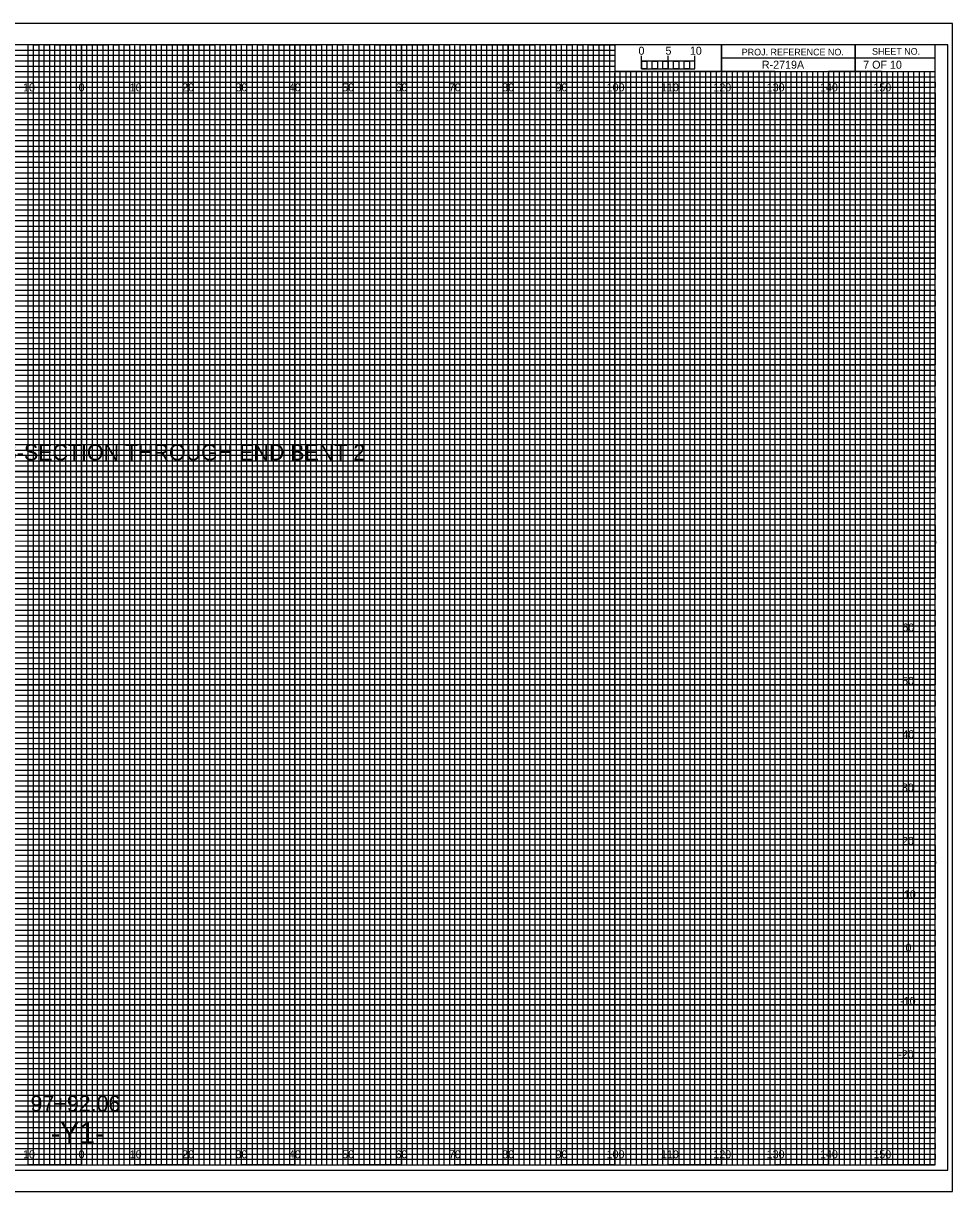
# Model space of a CAD drawing. Extents: x -13 to 886, y -5 to 434.
# Drawn here: x 149.1 to 323.3, y 215 to 434 of the extents above; entities that cross this region are included whole.
import ezdxf

# ---------------------------------------------------------------- set-up
doc = ezdxf.new("R2010")
doc.units = 0
for name, color, linetype in [('Prop Road Sect_ Boring - Header Labels from Geopak', 7, 'Continuous'), ('Prop XS Alignment Label', 7, 'Continuous'), ('Prop XS Bar Scale Labels', 7, 'Continuous'), ('Prop XS Elevation Labels', 7, 'Continuous'), ('Prop XS Offset Labels', 7, 'Continuous'), ('Prop XS Project Number', 7, 'Continuous'), ('Prop XS Sheet Number', 7, 'Continuous'), ('Prop XS Station Labels', 7, 'Continuous'), ('Sheet Cross Section CELL', 7, 'Continuous'), ('Sheet Cross Section Grid Major CELL', 7, 'Continuous'), ('Sheet Cross Section Grid Middle CELL', 7, 'Continuous'), ('Sheet Cross Section Grid Minor 1 CELL', 7, 'Continuous'), ('Sheet Cross Section Grid Minor 2 CELL', 7, 'Continuous'), ('Sheet Cross Section Scale CELL', 7, 'Continuous'), ('Sheet Cutting Line CELL', 7, 'Continuous'), ('Sheet DOT Grid CELL', 7, 'Continuous'), ('Sheet Plot Border Inside CELL', 7, 'Continuous'), ('Sheet Plot Border Outside CELL', 7, 'Continuous')]:
    doc.layers.add(name, color=color, linetype=linetype)

msp = doc.modelspace()

# ---------------------------------------------------------------- linework, layer by layer
at = {"layer": 'Sheet Cross Section CELL'}
for p, q in [((305, 430), (305, 425)), ((305, 425), (305, 430)), ((280, 427.5), (280, 425)), ((320, 427.49), (280, 427.49)), ((280, 425), (320, 425))]:
    msp.add_line(p, q, dxfattribs=at)
for points in [[(320, 430), (0, 430), (0, 220), (320, 220)], [(280, 430), (260, 430), (260, 425.03), (280, 425.03)], [(320, 430), (280, 430), (280, 425), (320, 425)]]:
    msp.add_lwpolyline(points, close=True, dxfattribs=at)
at = {"layer": 'Sheet Cross Section Grid Major CELL'}
for p, q in [((150, 430), (140, 430)), ((150, 220), (150, 430)), ((170, 430), (160, 430)), ((160, 430), (160, 220)), ((170, 220), (170, 430)), ((190, 430), (180, 430)), ((180, 430), (180, 220)), ((190, 220), (190, 430)), ((210, 430), (200, 430)), ((200, 430), (200, 220)), ((210, 220), (210, 430)), ((230, 430), (220, 430)), ((220, 430), (220, 220)), ((230, 220), (230, 430)), ((250, 430), (240, 430)), ((240, 430), (240, 220)), ((250, 220), (250, 430)), ((260, 430), (260, 220)), ((270, 220), (270, 425)), ((290, 425), (280, 425)), ((280, 425), (280, 220)), ((290, 220), (290, 425)), ((310, 425), (300, 425)), ((300, 425), (300, 220)), ((310, 220), (310, 425)), ((160, 220), (150, 220)), ((180, 220), (170, 220)), ((200, 220), (190, 220)), ((220, 220), (210, 220)), ((240, 220), (230, 220)), ((260, 220), (250, 220)), ((280, 220), (270, 220)), ((300, 220), (290, 220)), ((320, 220), (310, 220)), ((320, 220), (320, 220))]:
    msp.add_line(p, q, dxfattribs=at)
for points in [[(0, 420), (320, 420), (320, 410), (0, 410)], [(0, 400), (320, 400), (320, 390), (0, 390)], [(0, 380), (320, 380), (320, 370), (0, 370)], [(0, 360), (320, 360), (320, 350), (0, 350)], [(0, 340), (320, 340), (320, 330), (0, 330)], [(0, 320), (320, 320), (320, 310), (0, 310)], [(0, 300), (320, 300), (320, 290), (0, 290)], [(0, 280), (320, 280), (320, 270), (0, 270)], [(0, 260), (320, 260), (320, 250), (0, 250)], [(0, 240), (320, 240), (320, 230), (0, 230)]]:
    msp.add_lwpolyline(points, dxfattribs=at)
at = {"layer": 'Sheet Cross Section Grid Middle CELL'}
for points in [[(145, 220), (155, 220), (155, 430), (165, 430), (165, 220), (175, 220), (175, 430), (185, 430), (185, 220), (195, 220), (195, 430), (205, 430), (205, 220), (215, 220), (215, 430), (225, 430), (225, 220), (235, 220), (235, 430), (245, 430), (245, 220), (255, 220), (255, 430), (259.93, 430), (260, 430), (260, 425), (264.99, 425), (264.99, 220), (275, 220), (275, 425), (285, 425), (285, 220), (295, 220), (295, 425), (305, 425), (305, 220), (315, 220), (315, 425)], [(0, 425), (275, 425)], [(0, 405), (320, 405), (320, 415), (0, 415)], [(0, 385), (320, 385), (320, 395), (0, 395)], [(0, 365), (320, 365), (320, 375), (0, 375)], [(0, 345), (320, 345), (320, 355), (0, 355)], [(0, 325), (320, 325), (320, 335), (0, 335)], [(0, 305), (320, 305), (320, 315), (0, 315)], [(0, 285), (320, 285), (320, 295), (0, 295)], [(0, 265), (320, 265), (320, 275), (0, 275)], [(0, 245), (320, 245), (320, 255), (0, 255)], [(0, 225), (320, 225), (320, 235), (0, 235)]]:
    msp.add_lwpolyline(points, dxfattribs=at)
at = {"layer": 'Sheet Cross Section Grid Minor 1 CELL'}
for p, q in [((0, 429), (260, 429)), ((260, 427.98), (0, 427.98)), ((260, 429), (260, 427.98)), ((0, 427), (260, 427)), ((260, 425.89), (0, 425.89)), ((260, 427), (260, 425.89)), ((0, 424), (320, 424))]:
    msp.add_line(p, q, dxfattribs=at)
for points in [[(0, 423), (270, 423), (320, 423), (320, 422), (0, 422)], [(0, 421), (320, 421), (320, 419), (0, 419)], [(0, 418), (320, 418), (320, 417), (0, 416.98)], [(0, 416), (320, 416), (320, 414), (0, 414)], [(0, 413), (320, 413), (320, 412), (0, 412)], [(0, 411), (320, 411), (320, 409), (0, 409)], [(0, 408), (320, 408), (320, 407), (0, 407)], [(0, 406), (320, 406), (320, 404), (0, 404)], [(0, 403), (320, 403), (320, 402), (0, 402)], [(0, 401), (320, 401), (320, 399), (0, 399)], [(0, 398), (320, 398), (320, 397), (0, 397)], [(0, 396), (320, 396), (320, 393.95), (320, 393), (320, 392), (0, 392)], [(0, 394), (320, 394), (320, 393), (0, 393)], [(0, 391), (320, 391), (320, 389), (0, 389.03)], [(0, 389.03), (320, 389), (320, 388), (0, 388)], [(0, 387), (320, 387), (320, 386), (0, 386)], [(0, 384), (320, 384), (320, 383), (0, 383)], [(0, 382), (320, 382), (320, 381), (0, 381)], [(-0.07, 378.89), (320, 378.89), (320, 377.88), (-0.07, 377.88)], [(0, 377), (320, 377), (320, 376), (0, 376)], [(0, 374), (320, 374), (320, 373), (0, 373)], [(0, 372), (320, 372), (320, 371), (0, 371)], [(0, 369), (320, 369), (320, 368), (0, 368)], [(0, 367), (320, 367), (320, 366), (0, 366)], [(0, 364), (320, 364), (320, 363), (0, 363)], [(0, 362), (320, 362), (320, 361), (0, 361)], [(0, 359), (320, 359), (319.99, 357.98), (0, 358)], [(0, 357), (320, 357), (320, 356), (0, 356)], [(0, 354), (320, 354), (320, 353), (0, 353)], [(0, 352), (320, 352), (320, 351), (0, 351)], [(0, 349), (320, 349), (320, 348), (0, 348)], [(0, 347), (320, 347), (320, 346), (0, 346)], [(0, 344), (320, 344), (320, 343), (0, 343)], [(0, 342), (320, 342), (320, 341), (0, 341)], [(0, 339), (320, 339), (320, 338), (0, 338)], [(0, 336.99), (320.07, 336.91), (320, 336), (0, 336)], [(0, 334), (320, 334), (320, 333), (0, 333)], [(0, 332), (320, 332), (320, 331), (0, 331)], [(0, 329), (320, 329), (320, 328), (0, 328)], [(0, 327), (320, 327), (320, 326), (0, 326)], [(0, 324), (320, 324), (320, 323), (0, 323)], [(0, 322), (320, 322), (320, 321), (0, 321)], [(0, 319), (320, 319), (320, 318), (0, 318)], [(0, 317), (320, 317), (320, 316), (0, 316)], [(0, 314), (320, 314), (320, 313), (0, 313)], [(0, 312), (320, 312), (320, 311), (0, 311)], [(0, 309), (320, 309), (320, 308), (0, 308)], [(0, 307), (320, 307), (320, 306), (0, 306)], [(0, 304), (320, 304), (320, 303), (0, 303)], [(0, 302), (320, 302), (320, 301), (0, 301)], [(0, 299), (320, 299), (319.99, 297.98), (0, 298)], [(0, 297), (320, 297), (320, 296), (0, 296)], [(0, 294), (320, 294), (320, 293), (0, 293)], [(0, 292), (320, 292), (320, 291), (0, 291)], [(0, 289), (320, 289), (320, 288), (0, 288)], [(0, 287), (320, 287), (320, 286), (0, 286)], [(0, 284), (320, 284), (320, 283), (0, 283)], [(0, 282), (320, 282), (320, 281), (0, 281)], [(0, 279), (320, 279), (320, 278), (0, 278)], [(0, 276.99), (320.07, 276.91), (320, 276), (0, 276)], [(0, 274), (320, 274), (320, 273), (0, 273)], [(0, 272), (320, 272), (320, 271), (0, 271)], [(0, 269), (320, 269), (320, 268), (0, 268)], [(0, 267), (320, 267), (320, 266), (0, 266)], [(0, 264), (320, 264), (320, 263), (0, 263)], [(0, 262), (320, 262), (320, 261), (0, 261)], [(0, 259), (320, 259), (320, 258), (0, 258)], [(0, 257), (320, 257), (320, 256), (0, 256)], [(0, 254), (320, 254), (320, 253), (0, 253)], [(0, 252), (320, 252), (320, 251), (0, 251)], [(0, 249), (320, 249), (320, 248), (0, 248)], [(0, 247), (320, 247), (320, 246), (0, 246)], [(0, 244), (320, 244), (320, 243), (0, 243)], [(0, 242), (320, 242), (320, 241), (0, 241)], [(0, 239), (320, 239), (320, 238), (0, 238)], [(0, 237), (320, 237), (320, 236), (0, 236)], [(0, 234), (320, 234), (320, 233), (0, 233)], [(0, 232), (320, 232), (320, 231), (0, 231)], [(0, 229), (320, 229), (320, 228), (0, 228)], [(0, 227), (320, 227), (320, 226), (0, 226)], [(0, 224), (320, 224), (320, 223), (0, 223)], [(0, 222), (320, 222), (320, 221), (0, 221)]]:
    msp.add_lwpolyline(points, dxfattribs=at)
at = {"layer": 'Sheet Cross Section Grid Minor 2 CELL'}
for p, q in [((267, 425), (266.01, 425)), ((266.01, 425), (266.01, 220)), ((267, 220), (267, 425)), ((269, 425), (268, 425)), ((268, 425), (268, 220)), ((269, 220), (269, 425)), ((266.01, 220), (265, 220)), ((268, 220), (267, 220))]:
    msp.add_line(p, q, dxfattribs=at)
for points in [[(150, 220), (151, 220), (151, 430), (152, 430), (152, 220)], [(152, 220), (153, 220), (153, 430), (154, 430), (154, 220)], [(155, 220), (156, 220), (156, 430), (157, 430), (157, 220)], [(157, 220), (158, 220), (158, 430), (159, 430), (159, 220)], [(160, 220), (161, 220), (161, 430), (162, 430), (162, 220)], [(162, 220), (163, 220), (163, 430), (164, 430), (164, 220)], [(165, 220), (166, 220), (166, 430), (167, 430), (167, 220)], [(167, 220), (168, 220), (168, 430), (169, 430), (169, 220)], [(170, 220), (171, 220), (171, 430), (172, 430), (172, 220)], [(172, 220), (173, 220), (173, 430), (174, 430), (174, 220)], [(175, 220), (176, 220), (176, 430), (177, 430), (177, 220)], [(177, 220), (178, 220), (178, 430), (179, 430), (179, 220)], [(180, 220), (181, 220), (181, 430), (182, 430), (182, 220)], [(182, 220), (183, 220), (183, 430), (184, 430), (184, 220)], [(185, 220), (186, 220), (186, 430), (187, 430), (187, 220)], [(187, 220), (188, 220), (188, 430), (189, 430), (189, 220)], [(190, 220), (191, 220), (191, 430), (192, 430), (192, 220)], [(192, 220), (193, 220), (193, 430), (194, 430), (194, 220)], [(195, 220), (196, 220), (196, 430), (197, 430), (197, 220)], [(197, 220), (198, 220), (198, 430), (199, 430), (199, 220)], [(200, 220), (201, 220), (201, 430), (202, 430), (202, 220)], [(202, 220), (203, 220), (203, 430), (204, 430), (204, 220)], [(205, 220), (206, 220), (206, 430), (207, 430), (207, 220)], [(207, 220), (208, 220), (208, 430), (209, 430), (209, 220)], [(210, 220), (211, 220), (211, 430), (212, 430), (212, 220)], [(212, 220), (213, 220), (213, 430), (214, 430), (214, 220)], [(215, 220), (216, 220), (216, 430), (217, 430), (217, 220)], [(217, 220), (218, 220), (218, 430), (219, 430), (219, 220)], [(220, 220), (221, 220), (221, 430), (222, 430), (222, 220)], [(222, 220), (223, 220), (223, 430), (224, 430), (224, 220)], [(225, 220), (226, 220), (226, 430), (227, 430), (227, 220)], [(227, 220), (228, 220), (228, 430), (229, 430), (229, 220)], [(230, 220), (231, 220), (231, 430), (232, 430), (232, 220)], [(232, 220), (233, 220), (233, 430), (234, 430), (234, 220)], [(235, 220), (236, 220), (236, 430), (237, 430), (237, 220)], [(237, 220), (238, 220), (238, 430), (239, 430), (239, 220)], [(240, 220), (241, 220), (241, 430), (242, 430), (242, 220)], [(242, 220), (243, 220), (243, 430), (244, 430), (244, 220)], [(245, 220), (246, 220), (246, 430), (247, 430), (247, 220)], [(247, 220), (248, 220), (248, 430), (249, 430), (249, 220)], [(250, 220), (251, 220), (251, 430), (252, 430), (252, 220)], [(252, 220), (253, 220), (253, 430), (254, 430), (254, 220)], [(255, 220), (256, 220), (256, 430), (257, 430), (257, 220)], [(257, 220), (258, 220), (258, 430), (259, 430), (259, 220)], [(260, 220), (261, 220), (261, 425), (262.02, 425), (262.02, 220)], [(262, 220), (263, 220), (263, 425), (263.99, 425), (263.99, 220)], [(270, 220), (270.98, 220), (270.98, 425), (272, 425), (272, 220)], [(272, 220), (273, 220), (273, 425), (274.05, 425), (274.05, 220)], [(275, 220), (276, 220), (276, 425), (277, 425), (277, 220)], [(277, 220), (278, 220), (278, 425), (279, 425), (279, 220)], [(280, 220), (281, 220), (281, 425), (282, 425), (282, 220)], [(282, 220), (283, 220), (283, 425), (284, 425), (284, 220)], [(285, 220), (286, 220), (286, 425), (287, 425), (287, 220)], [(287, 220), (288, 220), (288, 425), (289, 425), (289, 220)], [(290, 220), (291, 220), (291, 425), (292, 425), (292, 220)], [(292, 220), (293, 220), (293, 425), (294, 425), (294, 220)], [(295, 220), (296, 220), (296, 425), (297, 425), (297, 220)], [(297, 220), (298, 220), (298, 425), (299, 425), (299, 220)], [(300, 220), (301, 220), (301, 425), (302, 425), (302, 220)], [(302, 220), (303, 220), (303, 425), (304, 425), (304, 220)], [(305, 220), (306, 220), (306, 425), (307, 425), (307, 220)], [(307, 220), (308, 220), (308, 425), (309, 425), (309, 220)], [(310, 220), (311, 220), (311, 425), (312, 425), (312, 220)], [(312, 220), (313, 220), (313, 425), (314, 425), (314, 220)], [(315, 220), (316, 220), (316, 425), (317, 425), (317, 220)], [(317, 220), (318, 220), (318, 425), (319, 425), (319, 220)]]:
    msp.add_lwpolyline(points, dxfattribs=at)
at = {"layer": 'Sheet Cross Section Scale CELL'}
for p, q in [((265, 425.49), (265, 427.9)), ((265, 426.9), (265, 427.9)), ((270, 425.49), (270, 427.9)), ((275, 425.49), (275, 427.9)), ((275, 426.9), (275, 427.9))]:
    msp.add_line(p, q, dxfattribs=at)
for points in [[(275, 426.9), (265, 426.9), (265, 425.49), (275, 425.49)], [(265, 426.9), (266, 426.9), (266, 425.49), (265, 425.49)], [(267, 426.9), (268, 426.9), (268, 425.49), (267, 425.49)], [(269, 426.9), (270, 426.9), (270, 425.49), (269, 425.49)], [(271, 426.9), (272, 426.9), (272, 425.49), (271, 425.49)], [(273, 426.9), (274, 426.9), (274, 425.49), (273, 425.49)]]:
    msp.add_lwpolyline(points, close=True, dxfattribs=at)
at = {"layer": 'Sheet Cutting Line CELL'}
for p, q in [((323.3, 434), (-13.4, 434)), ((-13.4, 215), (323.3, 215))]:
    msp.add_line(p, q, dxfattribs=at)
at = {"layer": 'Sheet DOT Grid CELL'}
for p, q in [((150, 220), (150, 430)), ((160, 220), (160, 430)), ((170, 220), (170, 430)), ((180, 220), (180, 430)), ((190, 220), (190, 430)), ((200, 220), (200, 430)), ((210, 220), (210, 430)), ((220, 220), (220, 430)), ((230, 220), (230, 430)), ((240, 220), (240, 430)), ((250, 220), (250, 430)), ((260, 220), (260, 424.69)), ((270, 220), (270, 424.69)), ((280, 220), (280, 424.69)), ((290, 220), (290, 424.69)), ((300, 220), (300, 424.69)), ((310, 220), (310, 424.69)), ((0, 420), (320, 420)), ((0, 410), (320, 410)), ((0, 400), (320, 400)), ((0, 390), (320, 390)), ((0, 380), (320, 380)), ((0, 370), (320, 370)), ((0, 360), (320, 360)), ((0, 350), (320, 350)), ((0, 340), (320, 340)), ((0, 330), (320, 330)), ((0, 320), (320, 320)), ((0, 310), (320, 310)), ((0, 300), (320, 300)), ((0, 290), (320, 290)), ((0, 280), (320, 280)), ((0, 270), (320, 270)), ((0, 260), (320, 260)), ((0, 250), (320, 250)), ((0, 240), (320, 240)), ((0, 230), (320, 230))]:
    msp.add_line(p, q, dxfattribs=at)
at = {"layer": 'Sheet Plot Border Inside CELL'}
msp.add_lwpolyline([(-10.8, 219), (322.4, 219), (322.4, 430), (-10.8, 430)], close=True, dxfattribs=at)
at = {"layer": 'Sheet Plot Border Outside CELL'}
msp.add_lwpolyline([(-13.4, 215), (323.3, 215), (323.3, 434), (-13.4, 434)], close=True, dxfattribs=at)

# ---------------------------------------------------------------- texts
at = {"layer": 'Prop Road Sect_ Boring - Header Labels from Geopak'}
msp.add_text('STRUCTURE 11 AND 12 CROSS-SECTION THROUGH END BENT 2', height=3, dxfattribs=at).set_placement((87.01, 352.09))
at = {"layer": 'Prop XS Alignment Label'}
msp.add_text('-Y1-', height=4, dxfattribs=at).set_placement((154.21, 224))
at = {"layer": 'Prop XS Bar Scale Labels'}
for s, p in [('5', (269.47, 428.12)), ('10', (274.04, 428.12))]:
    msp.add_text(s, height=1.5, dxfattribs=at).set_placement(p)
at = {"layer": 'Prop XS Elevation Labels'}
for s, p in [('60', (313.87, 320)), ('50', (313.82, 310)), ('40', (313.87, 300)), ('30', (313.78, 290)), ('20', (313.8, 280)), ('10', (314.17, 270)), ('0', (314.47, 260)), ('-10', (313.46, 250)), ('-20', (313.09, 240))]:
    msp.add_text(s, height=1.5, dxfattribs=at).set_placement(p)
at = {"layer": 'Prop XS Offset Labels'}
for s, p in [('10', (149.04, 421.25)), ('0', (159.45, 421.25)), ('0', (159.45, 421.25)), ('10', (169.04, 421.25)), ('20', (178.86, 421.25)), ('30', (188.86, 421.25)), ('40', (198.86, 421.25)), ('50', (208.86, 421.25)), ('60', (218.86, 421.25)), ('70', (228.86, 421.25)), ('80', (238.86, 421.25)), ('90', (248.86, 421.25)), ('100', (258.44, 421.25)), ('110', (268.62, 421.25)), ('120', (278.44, 421.25)), ('130', (288.44, 421.25)), ('140', (298.44, 421.25)), ('150', (308.44, 421.25)), ('10', (149.04, 221.25)), ('0', (159.45, 221.25)), ('0', (159.45, 221.25)), ('10', (169.04, 221.25)), ('20', (178.86, 221.25)), ('30', (188.86, 221.25)), ('40', (198.86, 221.25)), ('50', (208.86, 221.25)), ('60', (218.86, 221.25)), ('70', (228.86, 221.25)), ('80', (238.86, 221.25)), ('90', (248.86, 221.25)), ('100', (258.44, 221.25)), ('110', (268.62, 221.25)), ('120', (278.44, 221.25)), ('130', (288.44, 221.25)), ('140', (298.44, 221.25)), ('150', (308.44, 221.25))]:
    msp.add_text(s, height=1.5, dxfattribs=at).set_placement(p)
at = {"layer": 'Prop XS Project Number'}
msp.add_text('R-2719A', height=1.5, dxfattribs=at).set_placement((287.54, 425.5))
at = {"layer": 'Prop XS Sheet Number'}
msp.add_text('7 OF 10', height=1.5, dxfattribs=at).set_placement((306.54, 425.5))
at = {"layer": 'Prop XS Station Labels'}
msp.add_text('97+92.06', height=3, dxfattribs=at).set_placement((150.44, 230.01))
at = {"layer": 'Sheet Cross Section CELL'}
for s, p in [('PROJ. REFERENCE NO.', (283.77, 427.99)), ('SHEET NO.', (308.19, 428.12))]:
    msp.add_text(s, height=1.25, dxfattribs=at).set_placement(p)
at = {"layer": 'Sheet Cross Section Scale CELL'}
msp.add_text('0', height=1.5, dxfattribs=at).set_placement((264.41, 428.12))

doc.saveas('drawing.dxf')
